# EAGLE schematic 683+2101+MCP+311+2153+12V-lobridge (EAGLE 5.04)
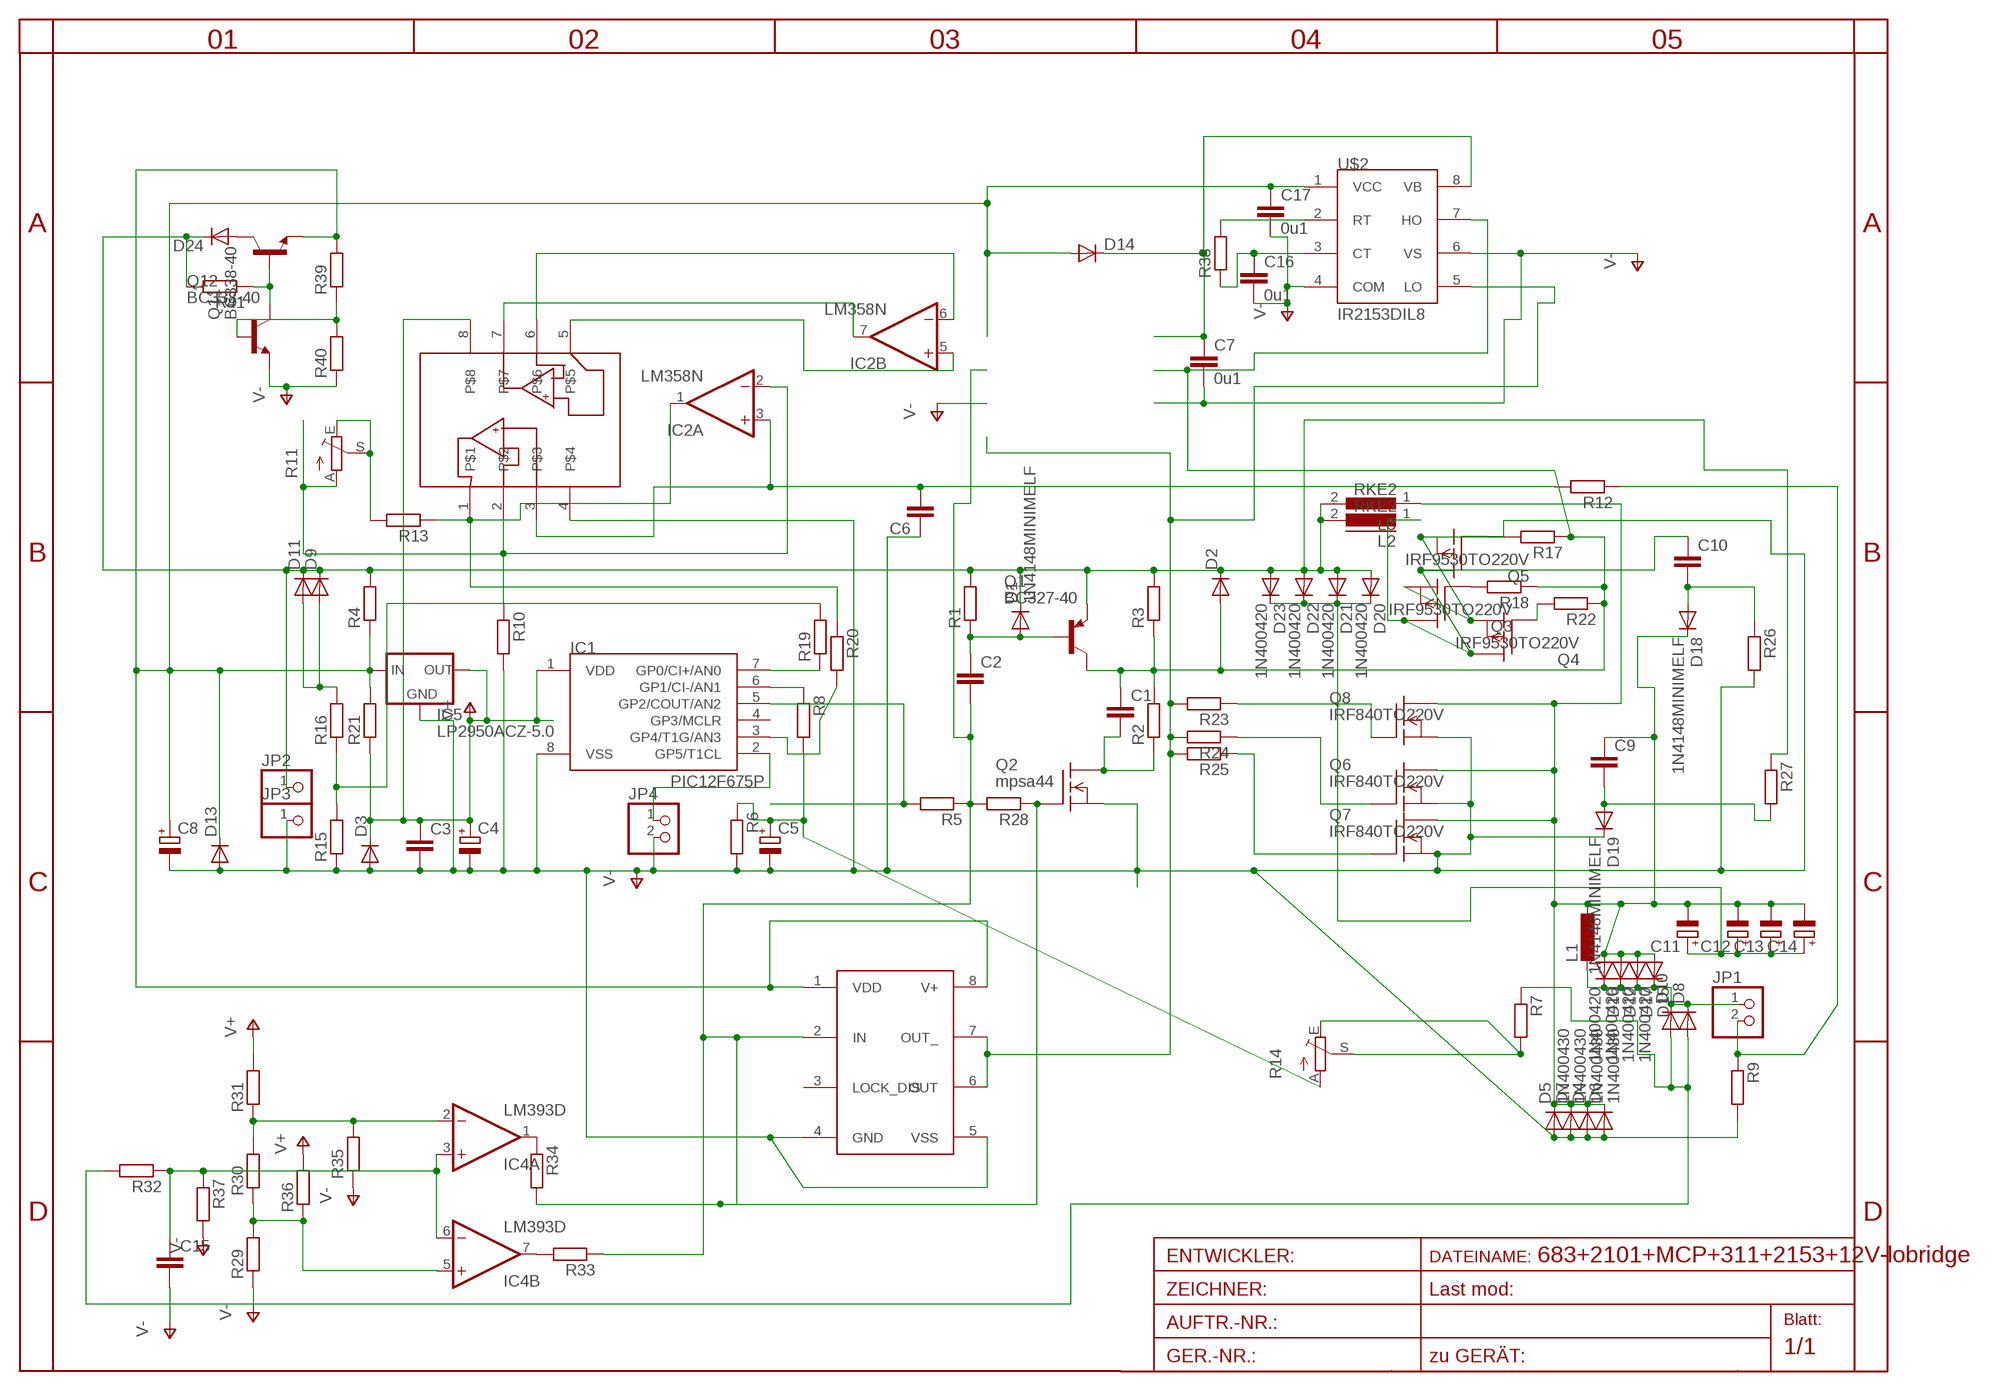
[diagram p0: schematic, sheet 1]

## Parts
C1  C-EU225-074X268  [C225-074X268]
C2  C-EU225-062X268  [C225-062X268]
C3  C-EU050-025X075  [C050-025X075]
C4  CPOL-EUE2.5-7  [E2,5-7]
C5  CPOL-EU5-13  [2,5-5-FLAT]
C6  C-EU025_050-025X075  [C025_050-025X075]
C7  0u1  C-EU050-025X075  [C050-025X075]
C8  CPOL-EU5-13  [2,5-5-FLAT]
C9  C-EUC1812  [C1812]
C10  C-EUC1812K  [C1812K]
C11  CPOL-EUSANYO_SMD_E7  [SANYO-OSCON_SMD_E7]
C12  CPOL-EUSANYO_SMD_E7  [SANYO-OSCON_SMD_E7]
C13  CPOL-EUSANYO_SMD_E7  [SANYO-OSCON_SMD_E7]
C14  CPOL-EUSANYO_SMD_E7  [SANYO-OSCON_SMD_E7]
C15  C-EU025-025X050  [C025-025X050]
C16  0u1  C-EU025-050X050  [C025-050X050]
C17  0u1  C-EU050-030X075  [C050-030X075]
D1  1N4148MINIMELF  [MINIMELF]
D2  DIODE-D-5  [D-5]
D3  DIODE-D-2.5  [D-2.5]
D4  1N400430  [DO41-30]
D5  1N400430  [DO41-30]
D6  1N400430  [DO41-30]
D7  1N400430  [DO41-30]
D8  DIODE-D-2.5  [D-2.5]
D9  DIODE-D-2.5  [D-2.5]
D10  DIODE-DO41-30  [DO41-30]
D11  DIODE-D-10  [D-10]
D12  1N400420  [DO41-20]
D13  DIODE-D-2.5  [D-2.5]
D14  DIODE-D-5  [D-5]
D15  1N400420  [DO41-20]
D16  1N400420  [DO41-20]
D17  1N400420  [DO41-20]
D18  1N4148MINIMELF  [MINIMELF]
D19  1N4148MINIMELF  [MINIMELF]
D20  1N400420  [DO41-20]
D21  1N400420  [DO41-20]
D22  1N400420  [DO41-20]
D23  1N400420  [DO41-20]
D24  DIODE-D-7.5  [D-7.5]
IC1  PIC12F675P  [DIL8]
IC2  LM358N  [DIL08]
IC3  TC4432X  [SO-08]
IC4  LM393D  [SO08]
IC5  LP2950ACZ-5.0  [TO92]
JP1  PINHD-1X2  [1X02]
JP2  PINHD-1X1  [1X01]
JP3  PINHD-1X1  [1X01]
JP4  PINHD-1X2  [1X02]
L1  L-EU0204/7  [0204/7]
L2  RKE2  [RKE2]
L3  RKE2  [RKE2]
Q1  BC327-40  [TO92-EBC]
Q2  mpsa44  TN0604N3  [TO-92]
Q3  IRF9530TO220V  [TO220V]
Q4  IRF9530TO220V  [TO220V]
Q5  IRF9530TO220V  [TO220V]
Q6  IRF840TO220V  [TO220V]
Q7  IRF840TO220V  [TO220V]
Q8  IRF840TO220V  [TO220V]
Q11  BC338-40  [TO92-EBC]
Q12  BC338-40  [TO92-EBC]
R1  R-EU_0204/2V  [0204V]
R2  R-EU_0207/25  [0207/25]
R3  R-EU_0204/2V  [0204V]
R4  R-EU_0207/10  [0207/10]
R5  R-EU_0207/40  [0207/40]
R6  R-EU_0207/10  [0207/10]
R7  R-EU_0207/15  [0207/15]
R8  R-EU_0207/10  [0207/10]
R9  R-EU_0207/10  [0207/10]
R10  R-EU_0207/15  [0207/15]
R11  TRIM_EU-CIP20C-4MM  [CIP20C-4MM]
R12  R-EU_0207/30  [0207/30]
R13  R-EU_0207/40  [0207/40]
R14  TRIM_EU-CIP20C-4MM  [CIP20C-4MM]
R15  R-EU_0204/5  [0204/5]
R16  R-EU_0207/25  [0207/25]
R17  R-EU_R1206  [R1206]
R18  R-EU_R1206  [R1206]
R19  R-EU_0204/5  [0204/5]
R20  R-EU_0204/5  [0204/5]
R21  R-EU_0207/10  [0207/10]
R22  R-EU_R1206  [R1206]
R23  R-EU_R1206  [R1206]
R24  R-EU_R1206  [R1206]
R25  R-EU_R1206  [R1206]
R26  R-EU_0207/25  [0207/25]
R27  R-EU_0207/30  [0207/30]
R28  R-EU_R0805  [R0805]
R29  R-EU_0204/5  [0204/5]
R30  R-EU_0204/5  [0204/5]
R31  R-EU_0204/5  [0204/5]
R32  R-EU_0207/40  [0207/40]
R33  R-EU_0207/12  [0207/12]
R34  R-EU_0207/20  [0207/20]
R35  R-EU_0204/5  [0204/5]
R36  R-EU_0204/5  [0204/5]
R37  R-EU_0204/5  [0204/5]
R38  R-EU_0204/2V  [0204V]
R39  R-EU_0207/10  [0207/10]
R40  R-EU_0204/2V  [0204V]
R41  R-EU_0207/10  [0207/10]
U$1  MCP6042SOIC  [SO-08]
U$2  IR2153DIL8  [DIL08]

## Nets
BB: C2.2 IC3.2(IN) Q2.2(G) R5.1 R28.1 R28.2 R33.1 R34.2
CT: C16.1 R38.1 U$2.3(CT)
DRAIN: C9.1 C11.- C12.- C13.- C14.- D4.C D5.C D6.C D7.C D12.A D15.A D16.A D17.A D18.C L1.1 L3.1 Q6.2(D) Q7.2(D) Q8.2(D)
GATE: C1.1 D2.A Q1.C R2.2 R3.1 R17.1 R18.1 R22.1 U$2.7(HO)
MPOINT: C5.+ R6.1 R8.2 R14.A
N$1: C1.2 Q2.3(D) R2.1
N$2: IC2.6(B:-IN) U$1.6
N$3: IC1.5(GP2/COUT/AN2) R5.2
N$4: Q3.1(G) R18.2
N$5: IC1.6(GP1/CI-/AN1) R8.1
N$6: IC2.2(A:-IN) R10.1 R11.A U$1.2
N$7: IC2.1(A:OUT) R13.1 R20.1 U$1.1
N$9: C6.2 IC2.3(A:+IN) R12.2 U$1.3
N$10: R7.2 R14.E R14.S
N$11: Q5.1(G) R17.2
N$12: R15.2 R16.1 R19.2
N$13: D9.A D11.A R16.2
N$14: IC1.7(GP0/CI+/AN0) R19.1
N$15: IC1.2(GP5/T1CL) JP4.1
N$16: D8.A D10.A R7.1 R32.2
N$17: IC1.3(GP4/T1G/AN3) R20.2
N$18: IC2.5(B:+IN) U$1.5
N$19: C15.1 IC4.3(A:+IN) IC4.6(B:-IN) R32.1 R37.1
N$20: IC2.7(B:OUT) U$1.7
N$21: C10.1 L2.1 Q3.2(D) Q4.2(D) Q5.2(D)
N$22: IC4.7(B:OUT) R33.2
N$23: Q4.1(G) R22.2
N$24: C10.2 D18.A R26.1
N$25: Q7.1(G) R25.1
N$26: Q6.1(G) R24.1
N$27: Q8.1(G) R23.1
N$28: C9.2 D19.A R27.2
N$29: R11.E R11.S R13.2
N$30: IC4.1(A:OUT) R34.1
N$31: C11.+ C12.+ C13.+ C14.+ D20.C D21.C D22.C D23.C
N$32: IC4.5(B:+IN) R29.2 R30.1 R36.1
N$33: IC3.6(OUT) IC3.7(OUT_) R23.2 R24.2 R25.2 U$2.5(LO)
N$34: IC4.2(A:-IN) R30.2 R31.1 R35.2
N$36: D24.A Q11.C
N$38: Q11.B Q12.C R41.1
N$40: R38.2 U$2.2(RT)
N$41: Q12.B R39.1 R40.2
OUT+: D8.C D10.C D12.C D15.C D16.C D17.C JP1.1 L1.2
OUT-: JP1.2 R9.1 R12.1
TB: C2.1 D1.A Q1.B R1.1
V+: C3.1 C4.+ D3.C IC1.1(VDD) IC5.1(OUT) R21.1 R31.2 R36.2 U$1.8
V-: C3.2 C4.- C5.- C6.1 C7.2 C8.- C15.2 C16.2 C17.2 D3.A D4.A D5.A D6.A D7.A D13.A D19.C IC1.8(VSS) IC3.4(GND) IC3.5(VSS) IC5.2(GND) JP3.1 JP4.2 Q2.1(S) Q3.3(S) Q4.3(S) Q5.3(S) Q6.3(S) Q7.3(S) Q8.3(S) Q12.E R6.2 R9.2 R10.2 R15.1 R26.2 R29.1 R35.1 R37.2 R40.1 U$1.4 U$2.4(COM) U$2.6(VS)
VB: C7.1 D14.C U$2.8(VB)
VCC: C8.+ C17.1 D13.C D14.A IC3.1(VDD) IC3.8(V+) IC5.3(IN) Q11.E R4.1 R21.2 R39.2 U$2.1(VCC)
VIN: D1.C D2.C D9.C D11.C D20.A D21.A D22.A D23.A D24.C JP2.1 L2.2 L3.2 Q1.E R1.2 R3.2 R4.2 R27.1 R41.2
Unconnected: IC1.4(GP3/MCLR) IC3.3(LOCK_DIS)

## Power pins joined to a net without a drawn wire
V+: IC2.8(P:V+) IC4.8(P:V+)
V-: IC2.4(P:V-) IC4.4(P:V-)

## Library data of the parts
C1-C3 C6 C7 C9 C10 C15-C17 = rcl-2:C-EU: CAPACITOR, European symbol
C4 C5 C8 C11-C14 = rcl-2:CPOL-EU: POLARIZED CAPACITOR, European symbol
D1 D18 D19 = diode-1:1N4148: DIODE
D2 D3 D8-D11 D13 D14 D24 = diode-1:DIODE-: DIODE
D4-D7 D12 D15-D17 D20-D23 = diode-1:1N4004: DIODE
IC1 = microchip-5:PIC12F6*: uPC nW 1k Program Flash memory 2x Timer Comparator 10b A/D converter/ 4xIN
IC2 = linear:LM358: OP AMP also LM158; LM258; LM2904 Source: http://cache.national.com/ds/LM/LM158.pdf
IC3 = microchip:TC4432
IC4 = linear:LM393: COMPARATOR
IC5 = v-reg:LP2950?*: Source: http://cache.national.com/ds/LP/LP2950.pdf
JP1 JP4 = pinhead:PINHD-1X2: PIN HEADER
JP2 JP3 = pinhead:PINHD-1X1: PIN HEADER
L1 = rcl-2:L-EU: INDUCTOR, European symbol
L2 L3 = inductors:RKE2: INDUCTOR
Q1 = transistor-pnp:BC327*: PNP Transistror
Q2 = transistor-fet:TN0604N3: N-Channel Enhancement MOSFET 40V; 4A; 0,75Ohm
Q3-Q5 = transistor-fet:IRF9530: P-Channel Enhancement MOSFET (HEXFET); -100V; -12A; 0,3Ohm
Q6-Q8 = transistor-fet:IRF840: N-Channel Enhancement MOSFET (HEXFET); 500V; 8A; 0,85Ohm
Q11 Q12 = transistor-npn:BC338*: NPN Transistor
R1-R10 R12 R13 R15-R41 = rcl-2:R-EU_: RESISTOR, European symbol
R11 R14 = pot:TRIM_EU-: POTENTIOMETER
U$1 = microchip-3:MCP6042
U$2 = irf-2:IR2153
